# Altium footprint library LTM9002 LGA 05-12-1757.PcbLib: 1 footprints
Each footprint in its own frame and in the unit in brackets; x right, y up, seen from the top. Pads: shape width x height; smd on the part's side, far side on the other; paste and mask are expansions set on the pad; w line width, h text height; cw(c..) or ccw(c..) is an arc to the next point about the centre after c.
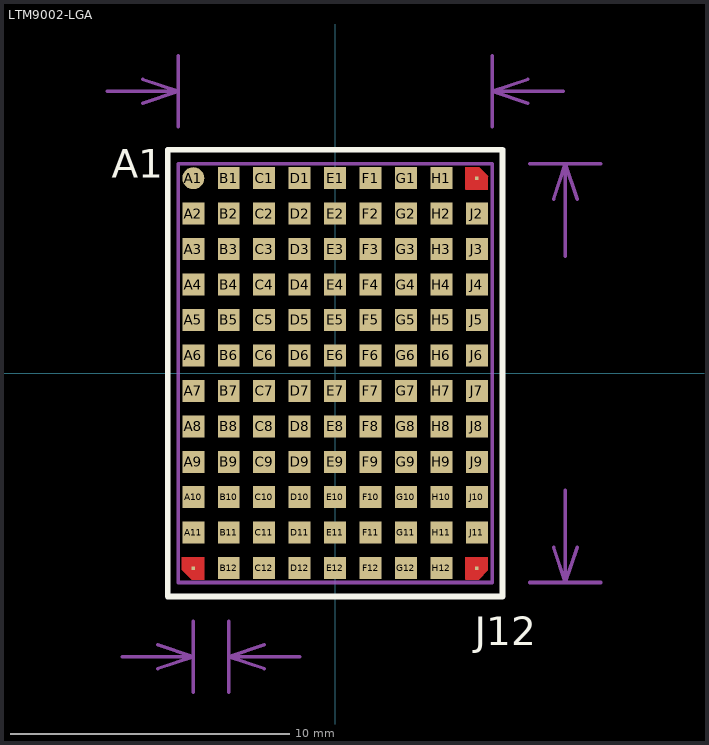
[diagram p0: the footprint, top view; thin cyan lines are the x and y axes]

## LTM9002-LGA [mil]
pads (108):
  round 31 smd paste-3.5 mask-3: A1(-200,275)
  rect 31x31 smd paste-3.5 mask-3: A2(-200,225) A3(-200,175) A4(-200,125) A5(-200,75) A6(-200,25) A7(-200,-25) A8(-200,-75) A9(-200,-125) A10(-200,-175) A11(-200,-225) B1(-150,275) B2(-150,225) B3(-150,175) B4(-150,125) B5(-150,75) B6(-150,25) B7(-150,-25) B8(-150,-75) B9(-150,-125) B10(-150,-175) B11(-150,-225) B12(-150,-275) C1(-100,275) C2(-100,225) C3(-100,175) C4(-100,125) C5(-100,75) C6(-100,25) C7(-100,-25) C8(-100,-75) C9(-100,-125) C10(-100,-175) C11(-100,-225) C12(-100,-275) D1(-50,275) D2(-50,225) D3(-50,175) D4(-50,125) D5(-50,75) D6(-50,25) D7(-50,-25) D8(-50,-75) D9(-50,-125) D10(-50,-175) D11(-50,-225) D12(-50,-275) E1(0,275) E2(0,225) E3(0,175) E4(0,125) E5(0,75) E6(0,25) E7(0,-25) E8(0,-75) E9(0,-125) E10(0,-175) E11(0,-225) E12(0,-275) F1(50,275) F2(50,225) F3(50,175) F4(50,125) F5(50,75) F6(50,25) F7(50,-25) F8(50,-75) F9(50,-125) F10(50,-175) F11(50,-225) F12(50,-275) G1(100,275) G2(100,225) G3(100,175) G4(100,125) G5(100,75) G6(100,25) G7(100,-25) G8(100,-75) G9(100,-125) G10(100,-175) G11(100,-225) G12(100,-275) H1(150,275) H2(150,225) H3(150,175) H4(150,125) H5(150,75) H6(150,25) H7(150,-25) H8(150,-75) H9(150,-125) H10(150,-175) H11(150,-225) H12(150,-275) J2(200,225) J3(200,175) J4(200,125) J5(200,75) J6(200,25) J7(200,-25) J8(200,-75) J9(200,-125) J10(200,-175) J11(200,-225)
  rect 5x5 smd paste-3.5 mask-3: A12(-200,-275) J1(200,275) J12(200,-275)
TopLayer:
  region: -215.5,-259.5 -184.5,-259.5 -184.5,-290.5 -202.5,-290.5 -215.5,-277.5
  region: 184.5,-259.5 215.5,-259.5 215.5,-277.5 202.5,-290.5 184.5,-290.5
  region: 184.5,290.5 202.5,290.5 215.5,277.5 215.5,259.5 184.5,259.5
  lines w0.39: -215.5,-277.5 -202.5,-290.5 -184.5,-290.5 -184.5,-259.5 -215.5,-259.5 -215.5,-277.5 ; 184.5,-290.5 202.5,-290.5 215.5,-277.5 215.5,-259.5 184.5,-259.5 184.5,-290.5 ; 184.5,259.5 184.5,290.5 202.5,290.5 215.5,277.5 215.5,259.5 184.5,259.5
TopOverlay:
  lines w8: -236.22,-314.96 236.22,-314.96 236.22,314.96 -236.22,314.96 -236.22,-314.96
  text "A1" at -314.96,275.59 h40
  text "J12" at 196.85,-383.86 h40
Mechanical16:
  lines w5: -321.46,397.64 -221.46,397.64 ; -300,-400 -200,-400 ; -271.46,380.97 -221.46,397.64 ; -271.46,414.3 -221.46,397.64 ; -250,-416.67 -200,-400 ; -250,-383.33 -200,-400 ; -221.46,347.64 -221.46,447.64 ; -200,-450 -200,-350 ; -150,-450 -150,-350 ; -100,-416.67 -150,-400 ; -100,-383.33 -150,-400 ; -50,-400 -150,-400 ; 221.46,347.64 221.46,447.64 ; 271.46,380.97 221.46,397.64 ; 271.46,414.3 221.46,397.64 ; 274.8,-295.28 374.8,-295.28 ; 274.8,295.28 374.8,295.28 ; 308.14,-245.28 324.8,-295.28 ; 308.14,245.28 324.8,295.28 ; 321.46,397.64 221.46,397.64 ; 324.8,-164.95 324.8,-295.28 ; 324.8,164.95 324.8,295.28 ; 341.47,-245.28 324.8,-295.28 ; 341.47,245.28 324.8,295.28 ; -221.46,-295.28 221.46,-295.28 221.46,295.28 -221.46,295.28 -221.46,-295.28
  text "15 (mm)" at 294.81,154.95 h50
  text "11.25 (mm)" at -218.5,469.49 h50
  text "1.27 (mm)" at -375.77,-519.97 h50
